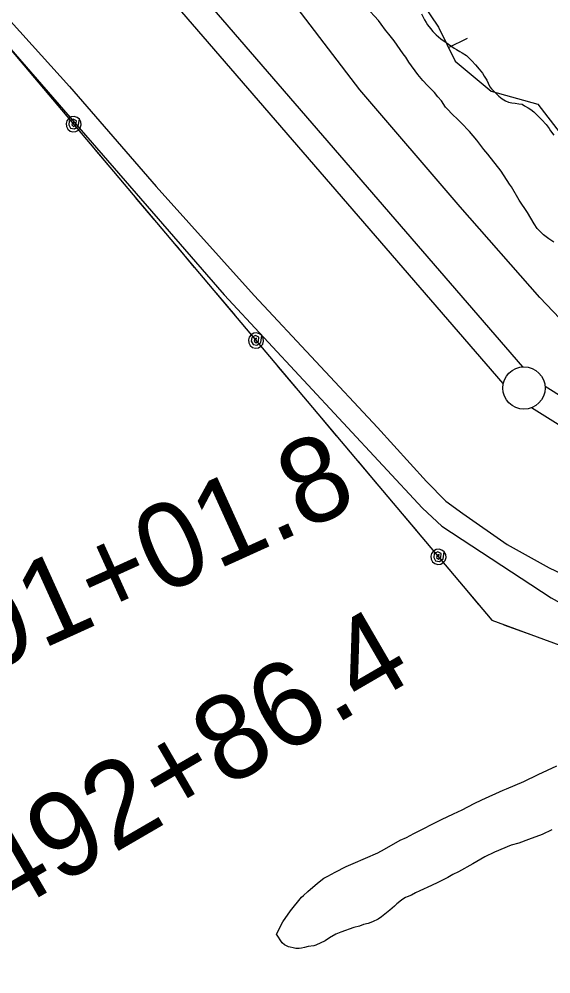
# Model space of a CAD drawing. Extents: x 3187622 to 3225504, y 800805 to 826213.
# Drawn here: x 3201448 to 3202076, y 810681 to 811808 of the extents above; entities that cross this region are included whole.
import ezdxf

# ---------------------------------------------------------------- set-up
doc = ezdxf.new("R2010")
doc.units = 0
for name, color, linetype in [('V-BORW-LINE', 7, 'Continuous'), ('V-LEVE-TOET', 7, 'Continuous'), ('V-SITE-VEGE', 7, 'Continuous'), ('V-SURV-IDEN', 7, 'Continuous'), ('V-SURV-LINE', 7, 'Continuous'), ('V-TOPO-SHOR', 7, 'Continuous'), ('V-UTIL-LINE', 7, 'Continuous')]:
    doc.layers.add(name, color=color, linetype=linetype)

msp = doc.modelspace()

# ---------------------------------------------------------------- linework, layer by layer
at = {"layer": 'V-BORW-LINE'}
msp.add_line((3201954.8, 811774.6), (3201977.2, 811785.7), dxfattribs=at)
msp.add_lwpolyline([(3201892.3, 811874), (3201942.9, 811798.7), (3201962.8, 811758.4), (3202005.2, 811723.3), (3202060.4, 811707.7), (3202086.7, 811673.7)], dxfattribs=at)
at = {"layer": 'V-LEVE-TOET'}
for points in [[(3203305.1, 811009.6), (3203190.5, 811042), (3203058.6, 811080.2), (3202898.7, 811132.1), (3202743.2, 811184.5), (3202585.4, 811236.6), (3202438.2, 811285.5), (3202344.3, 811319.5), (3202250.6, 811354.7), (3202195.3, 811375.8), (3202169.1, 811389.3), (3202152.1, 811402.4), (3202134, 811414.3), (3202117.4, 811427.3), (3202094.3, 811446.4), (3202062.5, 811479.7), (3201968.6, 811586.5), (3201850.1, 811724.7), (3201675.3, 811953.5)], [(3201404.1, 811842.6), (3201507.4, 811728.6), (3201609.5, 811610.7), (3201725.5, 811482), (3201870.8, 811326.3), (3201928.9, 811262.3), (3201951.5, 811239.3), (3201971.9, 811224.6), (3202023.9, 811188.2), (3202073.8, 811160.7), (3202096.2, 811150.1)]]:
    msp.add_lwpolyline(points, dxfattribs=at)
at = {"layer": 'V-SITE-VEGE'}
for points in [[(3202079.1, 811544.9), (3202073.2, 811549), (3202066.9, 811553.5), (3202063.7, 811556.7), (3202059.7, 811561.2), (3202056.1, 811566.7), (3202048, 811579.9), (3202038.1, 811594.4), (3202029.1, 811610.3), (3202026.9, 811613.4), (3202017, 811628.9), (3202001.2, 811648.9), (3201996.7, 811654.3), (3201988.2, 811665.2), (3201979.6, 811675.7), (3201976.5, 811678.8), (3201972.9, 811682.5), (3201966.5, 811688.9), (3201958.4, 811696.6), (3201954.4, 811701.1), (3201951.2, 811704.3), (3201946.7, 811711.6), (3201942.2, 811716.6), (3201938.2, 811721.6), (3201930.1, 811729.8), (3201924.7, 811735.7), (3201918.8, 811742.9), (3201908, 811757.5), (3201904.4, 811763.4), (3201901.3, 811767), (3201890.5, 811782.4), (3201884.2, 811790.2), (3201880.6, 811795.2), (3201875.2, 811802), (3201872, 811806.5), (3201857.6, 811822.4)], [(3201922.9, 811814.5), (3201926.5, 811807.3), (3201928.4, 811804.1), (3201930, 811801.5), (3201933.4, 811797.1), (3201936.4, 811793.6), (3201940.4, 811789.6), (3201945.7, 811784.8), (3201951.9, 811780.6), (3201954.9, 811778.5), (3201957.7, 811776.8), (3201961.6, 811773.8), (3201964.1, 811772.2), (3201968.3, 811770.1), (3201971.1, 811768.4), (3201975.9, 811765.2), (3201979.4, 811762.1), (3201982.4, 811758.9), (3201986.5, 811754), (3201990.9, 811749.1), (3201994.8, 811744.4), (3201997.1, 811740.7), (3201999.9, 811736.1), (3202001.5, 811732.6), (3202003.8, 811728.4), (3202005.6, 811725.9), (3202010.3, 811721), (3202014.4, 811717.2), (3202018.1, 811714), (3202022.3, 811711.6), (3202025.5, 811710.2), (3202029.4, 811709.3), (3202033.6, 811708.8), (3202037.8, 811708.1), (3202041.7, 811707.6), (3202044.7, 811706), (3202048.7, 811703.6), (3202052.1, 811701.5), (3202055.6, 811698.8), (3202057.9, 811696.4), (3202062.3, 811692), (3202065, 811689.2), (3202070.1, 811683.6), (3202073.8, 811679), (3202075.4, 811676.4), (3202079.3, 811671.3)], [(3201849.8, 810737.8), (3201843.2, 810736), (3201827.8, 810730.8), (3201821.6, 810728.2), (3201814.5, 810723.9), (3201809.3, 810720.4), (3201798.2, 810715.2), (3201796, 810714.7), (3201789, 810713.9), (3201784.6, 810712.6), (3201781.1, 810711.7), (3201778.5, 810711.3), (3201774.5, 810711.3), (3201771.4, 810712.2), (3201767.9, 810713.1), (3201765.7, 810713.5), (3201763.5, 810714.4), (3201761.3, 810715.8), (3201758.3, 810718), (3201751.7, 810728.1), (3201759.3, 810743), (3201768.1, 810755.7), (3201781.4, 810771.9), (3201783.6, 810774.1), (3201788.9, 810778.5), (3201800.3, 810788.5), (3201807.8, 810794.2), (3201812.2, 810796.8), (3201821, 810801.6), (3201833.8, 810808.2), (3201842.2, 810811.6), (3201871.2, 810824.2), (3201879.2, 810828.6), (3201897.7, 810839.1), (3201905.2, 810842.5), (3201914, 810846.9), (3201946.6, 810863.5), (3201960.7, 810870.4), (3201970.8, 810875.2), (3201985.3, 810882.6), (3201994.1, 810887), (3202019.2, 810898.3), (3202023.2, 810899.6), (3202043.9, 810908.3), (3202060.6, 810916.6), (3202082.6, 810927)], [(3202077, 810851.5), (3202065.6, 810845.8), (3202049.3, 810840.2), (3202037.8, 810835.8), (3202029, 810833.2), (3202009.2, 810825), (3201997.8, 810819.7), (3201983.7, 810811.4), (3201966.5, 810801.8), (3201959.9, 810798.8), (3201954.2, 810795.3)], [(3201954.2, 810795.3), (3201944.5, 810790.5), (3201942.3, 810789.2), (3201934.8, 810785.7), (3201921.1, 810779.6), (3201915.9, 810777), (3201911, 810774.4), (3201906.2, 810772.2), (3201904, 810771.4), (3201899.6, 810768.8), (3201897.4, 810767), (3201893.8, 810763.9), (3201891.2, 810761.3), (3201885.4, 810756.5), (3201875.7, 810748.6), (3201871.8, 810746), (3201865.2, 810743), (3201859.9, 810740.8), (3201854.6, 810739.5), (3201849.8, 810737.8)]]:
    msp.add_lwpolyline(points, dxfattribs=at)
at = {"layer": 'V-SURV-LINE'}
for points in [[(3200848.5, 812777.7), (3202042.2, 811397.7)], [(3202019.5, 811378.1), (3200825.8, 812758.1)], [(3202068.9, 811374.9), (3202191.5, 811298.4)], [(3202175.6, 811272.9), (3202053, 811349.5)]]:
    msp.add_lwpolyline(points, dxfattribs=at)
msp.add_circle((3202043.9, 811372.8), 25, dxfattribs=at)
at = {"layer": 'V-TOPO-SHOR'}
msp.add_lwpolyline([(3201422.1, 811790.6), (3201690, 811482.7), (3201924.1, 811231), (3201946.8, 811209.8), (3202076.2, 811125.1), (3202102.5, 811110.6), (3202270.4, 811054), (3202404.7, 811008.5), (3202779.4, 810876.1), (3203057.9, 810770.9), (3203099.9, 810746.1), (3203148.1, 810710.8), (3203186.1, 810667.2), (3203211.7, 810635.1)], dxfattribs=at)
at = {"layer": 'V-UTIL-LINE'}
for points in [[(3199923.1, 813594.5), (3200640, 812717.8), (3202006.1, 811098.7), (3203128.7, 810686.1), (3203334.1, 810414.1), (3203687.1, 810134), (3205008, 808523.1), (3206197, 808326.5), (3208534.5, 807926.9), (3209217.7, 808075.2), (3210991.3, 807487.7), (3211714.8, 807276.3), (3211555.1, 806654.5), (3211454.6, 806207.4)], [(3201465.1, 811739.9), (3201487, 811713.9)], [(3201512.2, 811684.1), (3201512.9, 811686.9), (3201510.7, 811686.1), (3201510.1, 811683.4), (3201512.2, 811681.4), (3201514.9, 811683.5), (3201515.4, 811688.1), (3201511.5, 811690), (3201507.1, 811687.9), (3201506.5, 811683.4), (3201508.6, 811679.4), (3201513.3, 811678.6), (3201517.7, 811681.9), (3201519, 811689.9), (3201516.3, 811692.1), (3201512.9, 811693.1), (3201509.4, 811692.7), (3201506.4, 811691), (3201504.2, 811688.2), (3201503.2, 811684.9), (3201503.6, 811681.4), (3201505.3, 811678.3), (3201508, 811676.1), (3201511.4, 811675.1), (3201514.9, 811675.5), (3201518, 811677.2), (3201520.1, 811680), (3201521.1, 811683.3), (3201520.7, 811686.8), (3201519, 811689.9)], [(3201537.3, 811654.3), (3201559.2, 811628.3)], [(3201585, 811597.7), (3201606.9, 811571.8)], [(3201632.7, 811541.2), (3201654.7, 811515.2)], [(3201680.5, 811484.6), (3201702.4, 811458.6)], [(3201727.5, 811428.8), (3201728.3, 811431.6), (3201726.1, 811430.8), (3201725.4, 811428.2), (3201727.6, 811426.1), (3201730.3, 811428.2), (3201730.8, 811432.9), (3201726.9, 811434.7), (3201722.5, 811432.6), (3201721.9, 811428.1), (3201724, 811424.1), (3201728.7, 811423.3), (3201733.1, 811426.6), (3201734.4, 811434.6), (3201731.7, 811436.8), (3201728.3, 811437.8), (3201724.8, 811437.4), (3201721.7, 811435.7), (3201719.5, 811433), (3201718.6, 811429.6), (3201719, 811426.1), (3201720.7, 811423), (3201723.4, 811420.8), (3201726.8, 811419.9), (3201730.3, 811420.3), (3201733.3, 811422), (3201735.5, 811424.7), (3201736.5, 811428.1), (3201736.1, 811431.6), (3201734.4, 811434.6)], [(3201752.7, 811399), (3201774.6, 811373)], [(3201800.4, 811342.5), (3201822.3, 811316.5)], [(3201848.1, 811285.9), (3201870, 811259.9)], [(3201895.8, 811229.4), (3201917.8, 811203.4)], [(3201942.9, 811173.6), (3201943.7, 811176.3), (3201941.5, 811175.5), (3201940.8, 811172.9), (3201943, 811170.9), (3201945.7, 811172.9), (3201946.2, 811177.6), (3201942.3, 811179.4), (3201937.9, 811177.4), (3201937.3, 811172.8), (3201939.3, 811168.9), (3201944.1, 811168), (3201948.5, 811171.3), (3201949.8, 811179.4), (3201947.1, 811181.5), (3201943.7, 811182.5), (3201940.2, 811182.1), (3201937.1, 811180.4), (3201934.9, 811177.7), (3201934, 811174.3), (3201934.3, 811170.8), (3201936, 811167.8), (3201938.8, 811165.6), (3201942.2, 811164.6), (3201945.6, 811165), (3201948.7, 811166.7), (3201950.9, 811169.4), (3201951.9, 811172.8), (3201951.5, 811176.3), (3201949.8, 811179.4)], [(3201968.1, 811143.8), (3201990, 811117.8)], [(3202020.2, 811093.5), (3202052.1, 811081.8)]]:
    msp.add_lwpolyline(points, dxfattribs=at)

# ---------------------------------------------------------------- texts
at = {"layer": 'V-SURV-IDEN'}
for s, rotation, p in [('1491+01.8', 24.388, (3201271.7, 810972.1)), ('1492+86.4', 30.1629, (3201366.6, 810711.1))]:
    msp.add_text(s, height=100, rotation=rotation, dxfattribs=at).set_placement(p)

doc.saveas('drawing.dxf')
